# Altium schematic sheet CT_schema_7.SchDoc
size 368 x 333 mm
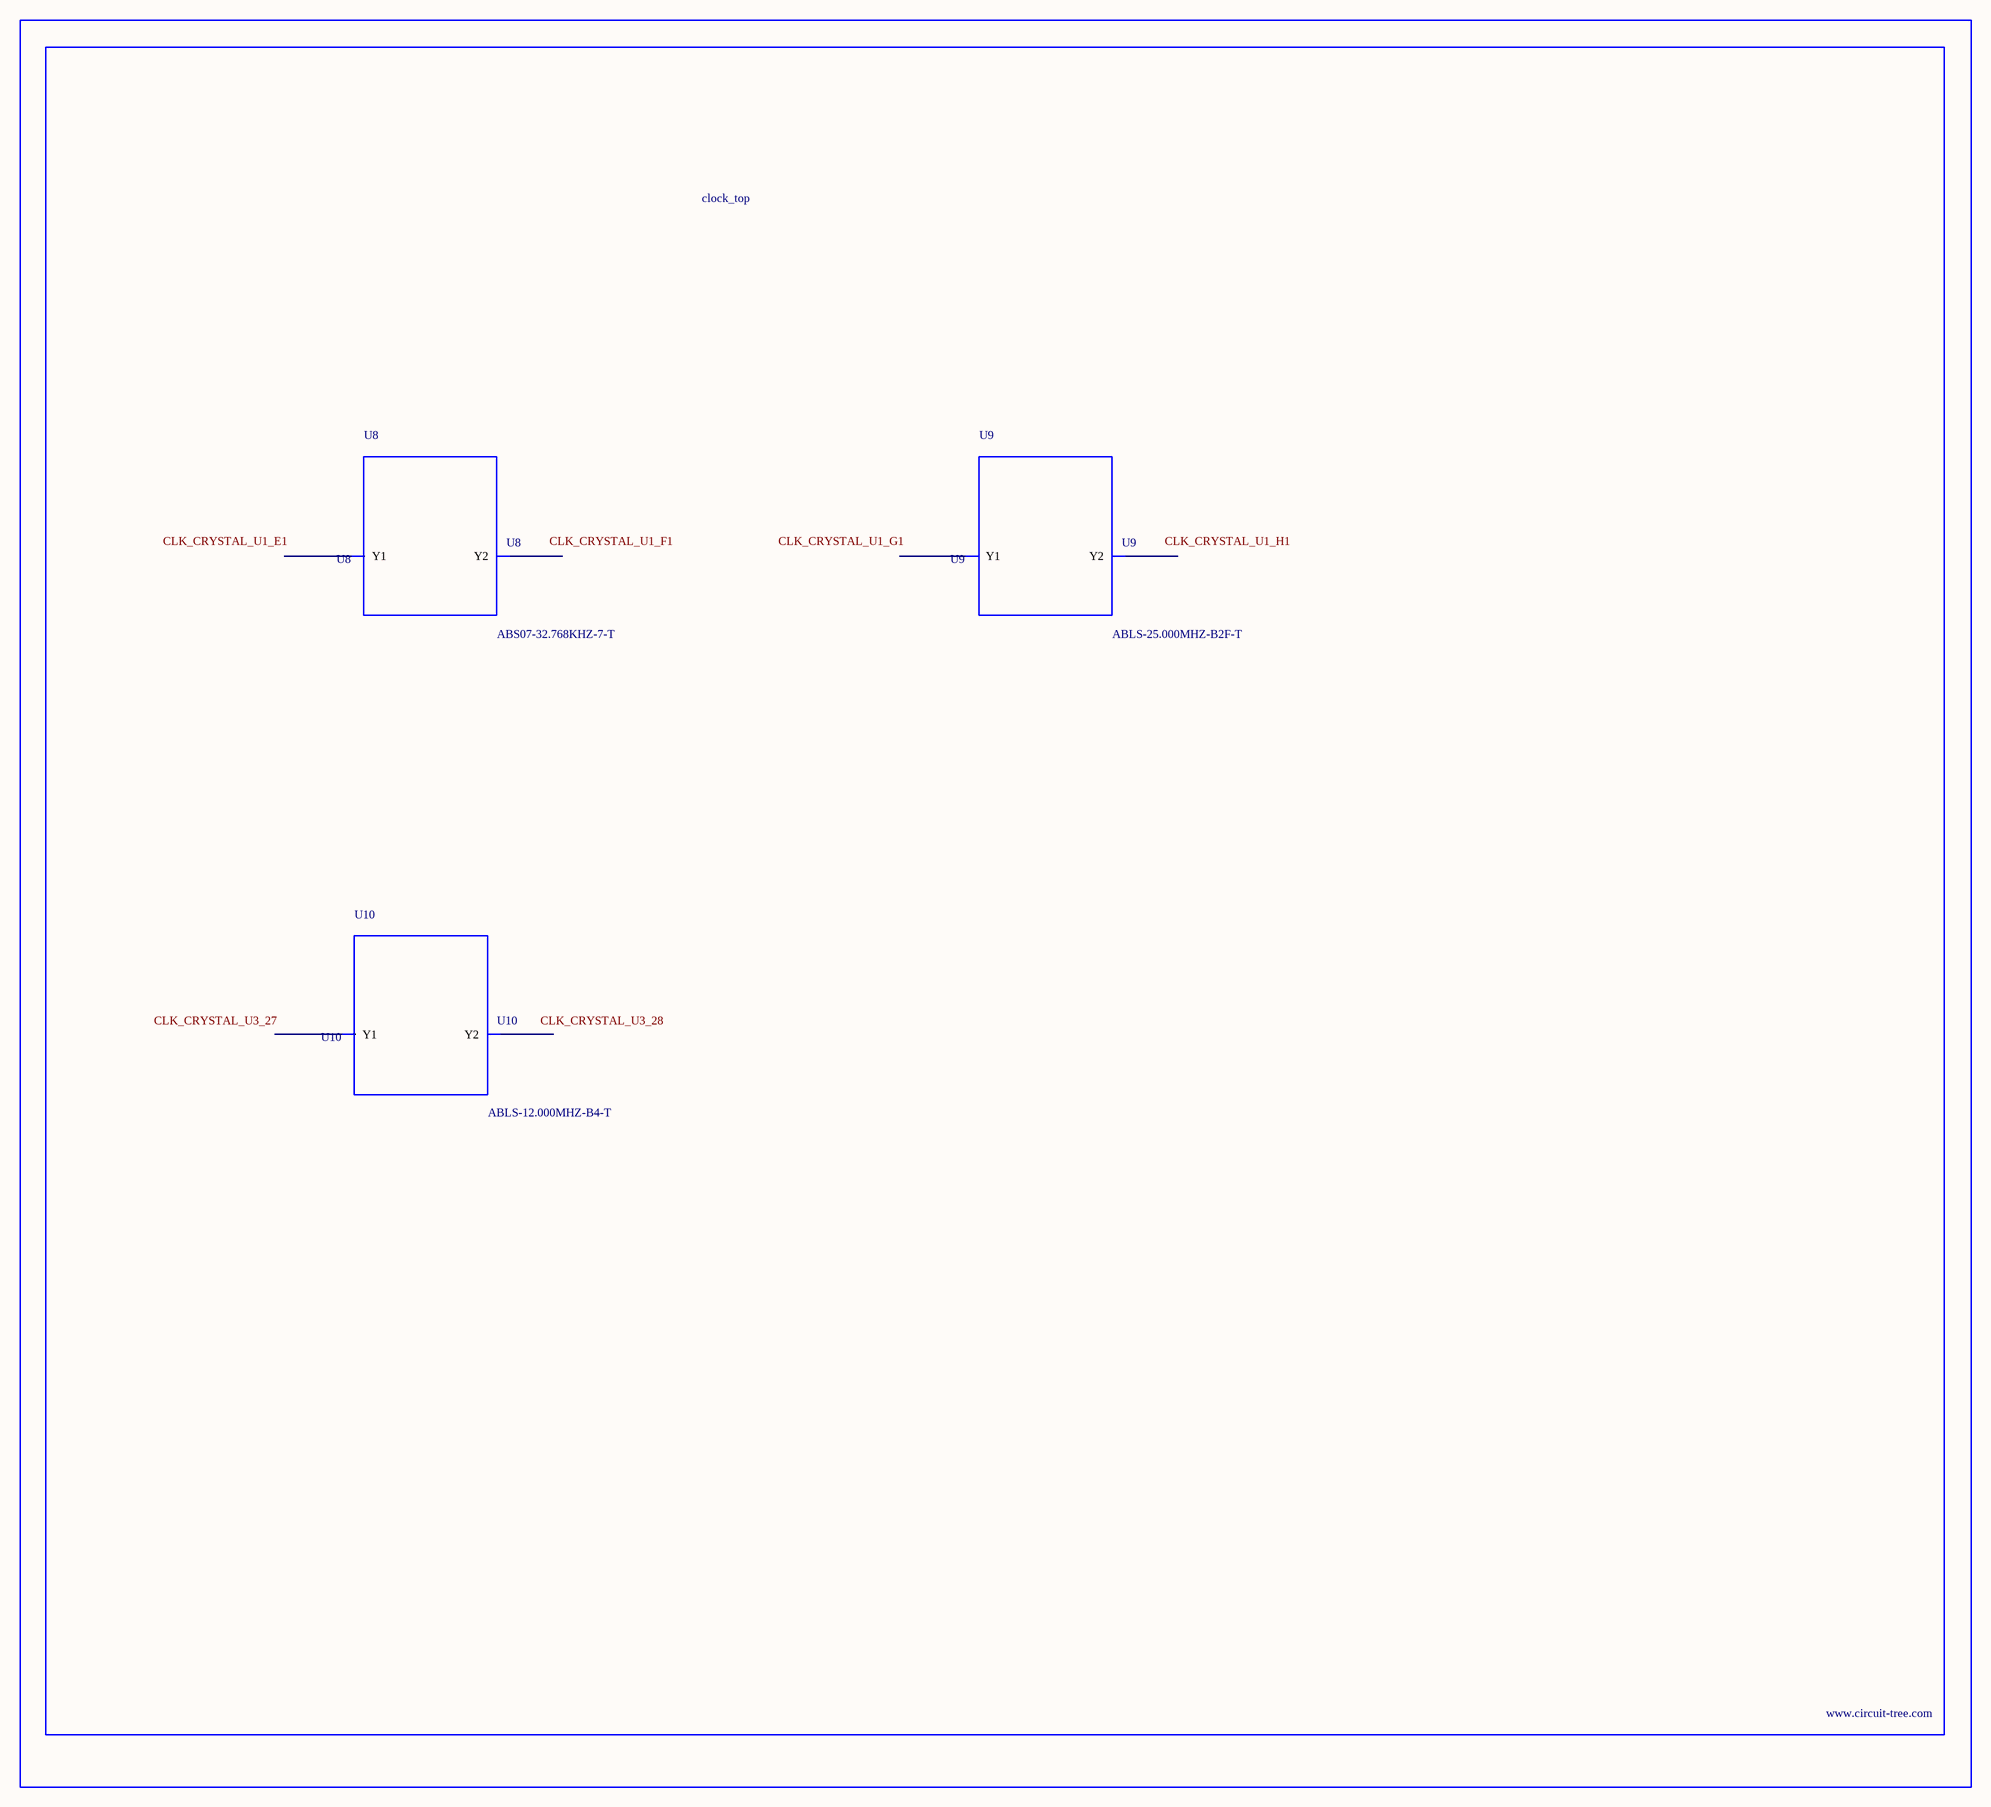
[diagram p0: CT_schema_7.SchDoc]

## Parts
BORDER6  (no value)
U8  ABS07-32.768KHZ-7-T  [ABS07-32.768KHZ-7-T]
U9  ABLS-25.000MHZ-B2F-T  [ABLS-25.000MHZ-B2F-T]
U10  ABLS-12.000MHZ-B4-T  [ABLS-12.000MHZ-B4-T]

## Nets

Not connected (* = marked no-connect by the designer): U8 1(Y1) 2(Y2); U9 1(Y1) 2(Y2); U10 1(Y1) 2(Y2)

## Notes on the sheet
- Labels drawn without touching a wire or pin: CLK_CRYSTAL_U1_E1, CLK_CRYSTAL_U1_F1, CLK_CRYSTAL_U1_G1, CLK_CRYSTAL_U1_H1, CLK_CRYSTAL_U3_27, CLK_CRYSTAL_U3_28

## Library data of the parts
BORDER6 = BORDER_PAGE6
